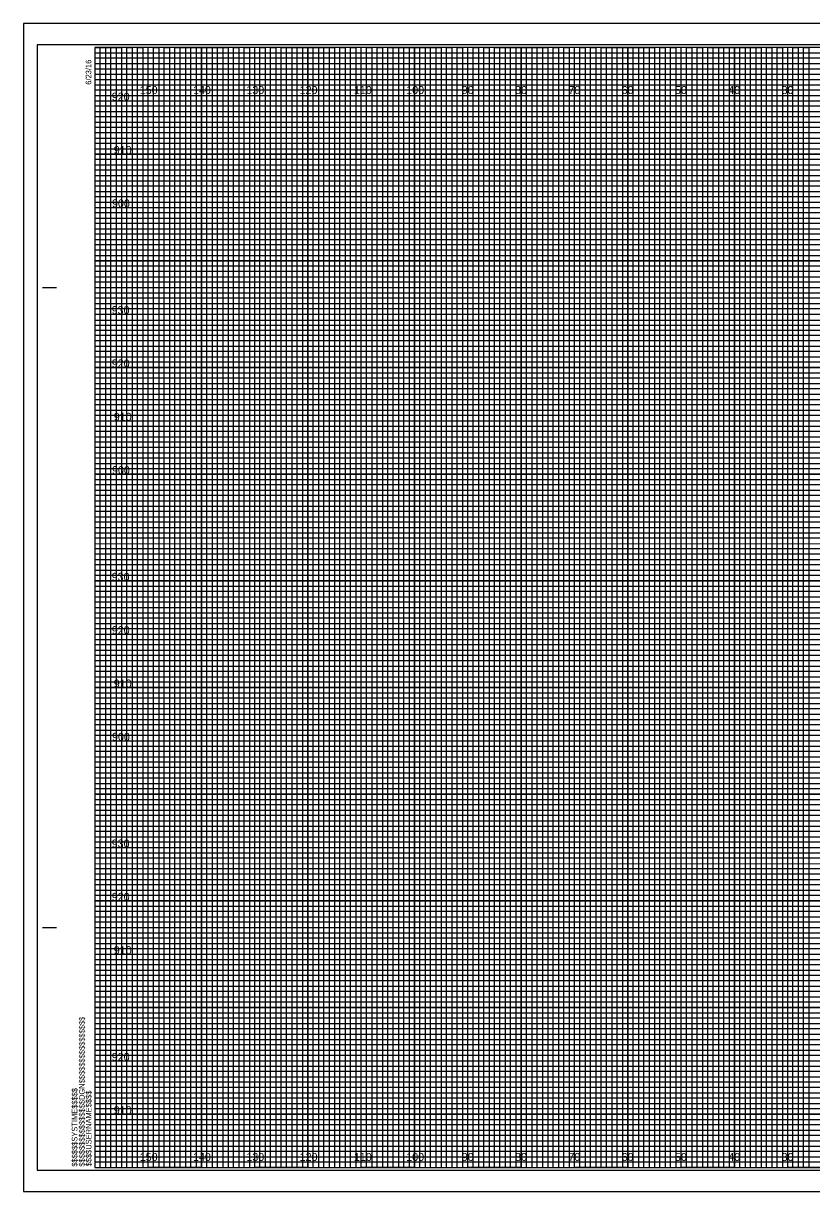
# Model space of a CAD drawing. Extents: x -13 to 323, y -4 to 214.
# Drawn here: x -13.4 to 134.5, y -4.5 to 214.5 of the extents above; entities that cross this region are included whole.
import ezdxf

# ---------------------------------------------------------------- set-up
doc = ezdxf.new("R2010")
doc.units = 0
for name, color, linetype in [('Exist XS Center Line Elevation Label', 7, 'Continuous'), ('Prop XS Elevation Labels', 7, 'Continuous'), ('Sheet Cross Section CELL', 7, 'Continuous'), ('Sheet Cross Section Grid Major CELL', 7, 'Continuous'), ('Sheet Cross Section Grid Middle CELL', 7, 'Continuous'), ('Sheet Cross Section Grid Minor 1 CELL', 7, 'Continuous'), ('Sheet Cross Section Grid Minor 2 CELL', 7, 'Continuous'), ('Sheet Cutting Line CELL', 7, 'Continuous'), ('Sheet DOT Grid CELL', 7, 'Continuous'), ('Sheet Plot Border Inside CELL', 7, 'Continuous'), ('Sheet Plot Border Outside CELL', 7, 'Continuous')]:
    doc.layers.add(name, color=color, linetype=linetype)

msp = doc.modelspace()

# ---------------------------------------------------------------- linework, layer by layer
at = {"layer": 'Sheet Cross Section CELL'}
for p, q in [((-9.8, 165), (-7.3, 165)), ((-9.7, 165), (-7.2, 165)), ((-9.8, 45), (-7.3, 45)), ((-9.7, 45), (-7.2, 45)), ((0, 0), (0, 0)), ((0, 0), (0, 0)), ((0, 0), (0, 0)), ((0, 0), (0, 0)), ((0, 0), (0, 0)), ((0, 0), (0, 0)), ((0, 0), (0, 0))]:
    msp.add_line(p, q, dxfattribs=at)
msp.add_lwpolyline([(320, 210), (0, 210), (0, 0), (320, 0)], close=True, dxfattribs=at)
at = {"layer": 'Sheet Cross Section Grid Major CELL'}
for p, q in [((10, 210), (0, 210)), ((10, 0), (10, 210)), ((30, 210), (20, 210)), ((20, 210), (20, 0)), ((30, 0), (30, 210)), ((50, 210), (40, 210)), ((40, 210), (40, 0)), ((50, 0), (50, 210)), ((70, 210), (60, 210)), ((60, 210), (60, 0)), ((70, 0), (70, 210)), ((90, 210), (80, 210)), ((80, 210), (80, 0)), ((90, 0), (90, 210)), ((110, 210), (100, 210)), ((100, 210), (100, 0)), ((110, 0), (110, 210)), ((130, 210), (120, 210)), ((120, 210), (120, 0)), ((130, 0), (130, 210)), ((20, 0), (10, 0)), ((40, 0), (30, 0)), ((60, 0), (50, 0)), ((80, 0), (70, 0)), ((100, 0), (90, 0)), ((120, 0), (110, 0)), ((140, 0), (130, 0))]:
    msp.add_line(p, q, dxfattribs=at)
for points in [[(0, 200), (320, 200), (320, 190), (0, 190)], [(0, 180), (320, 180), (320, 170), (0, 170)], [(0, 160), (320, 160), (320, 150), (0, 150)], [(0, 140), (320, 140), (320, 130), (0, 130)], [(0, 120), (320, 120), (320, 110), (0, 110)], [(0, 100), (320, 100), (320, 90), (0, 90)], [(0, 80), (320, 80), (320, 70), (0, 70)], [(0, 60), (320, 60), (320, 50), (0, 50)], [(0, 40), (320, 40), (320, 30), (0, 30)], [(0, 20), (320, 20), (320, 10), (0, 10)]]:
    msp.add_lwpolyline(points, dxfattribs=at)
at = {"layer": 'Sheet Cross Section Grid Middle CELL'}
for points in [[(0, 210), (5, 210), (5, 0), (15, 0), (15, 210), (25, 210), (25, 0), (35, 0), (35, 210), (45, 210), (45, 0), (55, 0), (55, 210), (65, 210), (65, 0), (75, 0), (75, 210), (85, 210), (85, 0), (95, 0), (95, 210), (105, 210), (105, 0), (115, 0), (115, 210), (125, 210), (125, 0), (135, 0)], [(0, 205), (275, 205)], [(0, 185), (320, 185), (320, 195), (0, 195)], [(0, 165), (320, 165), (320, 175), (0, 175)], [(0, 145), (320, 145), (320, 155), (0, 155)], [(0, 125), (320, 125), (320, 135), (0, 135)], [(0, 105), (320, 105), (320, 115), (0, 115)], [(0, 85), (320, 85), (320, 95), (0, 95)], [(0, 65), (320, 65), (320, 75), (0, 75)], [(0, 45), (320, 45), (320, 55), (0, 55)], [(0, 25), (320, 25), (320, 35), (0, 35)], [(0, 5), (320, 5), (320, 15), (0, 15)]]:
    msp.add_lwpolyline(points, dxfattribs=at)
at = {"layer": 'Sheet Cross Section Grid Minor 1 CELL'}
for p, q in [((0, 209), (260, 209)), ((260, 207.98), (0, 207.98)), ((0, 207.98), (0, 207)), ((0, 207), (260, 207)), ((260, 205.89), (0, 205.89)), ((0, 205.89), (0, 204)), ((0, 204), (320, 204))]:
    msp.add_line(p, q, dxfattribs=at)
for points in [[(0, 203), (270, 203), (320, 203), (320, 202), (0, 202)], [(0, 201), (320, 201), (320, 199), (0, 199)], [(0, 198), (320, 198), (320, 197), (0, 196.98)], [(0, 196), (320, 196), (320, 194), (0, 194)], [(0, 193), (320, 193), (320, 192), (0, 192)], [(0, 191), (320, 191), (320, 189), (0, 189)], [(0, 188), (320, 188), (320, 187), (0, 187)], [(0, 186), (320, 186), (320, 184), (0, 184)], [(0, 183), (320, 183), (320, 182), (0, 182)], [(0, 181), (320, 181), (320, 179), (0, 179)], [(0, 178), (320, 178), (320, 177), (0, 177)], [(0, 176), (320, 176), (320, 173.95), (320, 173), (320, 172), (0, 172)], [(0, 174), (320, 174), (320, 173), (0, 173)], [(0, 171), (320, 171), (320, 169), (0, 169.03)], [(0, 169.03), (320, 169), (320, 168), (0, 168)], [(0, 167), (320, 167), (320, 166), (0, 166)], [(0, 164), (320, 164), (320, 163), (0, 163)], [(0, 162), (320, 162), (320, 161), (0, 161)], [(-0.07, 158.89), (320, 158.89), (320, 157.88), (-0.07, 157.88)], [(0, 157), (320, 157), (320, 156), (0, 156)], [(0, 154), (320, 154), (320, 153), (0, 153)], [(0, 152), (320, 152), (320, 151), (0, 151)], [(0, 149), (320, 149), (320, 148), (0, 148)], [(0, 147), (320, 147), (320, 146), (0, 146)], [(0, 144), (320, 144), (320, 143), (0, 143)], [(0, 142), (320, 142), (320, 141), (0, 141)], [(0, 139), (320, 139), (319.99, 137.98), (0, 138)], [(0, 137), (320, 137), (320, 136), (0, 136)], [(0, 134), (320, 134), (320, 133), (0, 133)], [(0, 132), (320, 132), (320, 131), (0, 131)], [(0, 129), (320, 129), (320, 128), (0, 128)], [(0, 127), (320, 127), (320, 126), (0, 126)], [(0, 124), (320, 124), (320, 123), (0, 123)], [(0, 122), (320, 122), (320, 121), (0, 121)], [(0, 119), (320, 119), (320, 118), (0, 118)], [(0, 116.99), (320.07, 116.91), (320, 116), (0, 116)], [(0, 114), (320, 114), (320, 113), (0, 113)], [(0, 112), (320, 112), (320, 111), (0, 111)], [(0, 109), (320, 109), (320, 108), (0, 108)], [(0, 107), (320, 107), (320, 106), (0, 106)], [(0, 104), (320, 104), (320, 103), (0, 103)], [(0, 102), (320, 102), (320, 101), (0, 101)], [(0, 99), (320, 99), (320, 98), (0, 98)], [(0, 97), (320, 97), (320, 96), (0, 96)], [(0, 94), (320, 94), (320, 93), (0, 93)], [(0, 92), (320, 92), (320, 91), (0, 91)], [(0, 89), (320, 89), (320, 88), (0, 88)], [(0, 87), (320, 87), (320, 86), (0, 86)], [(0, 84), (320, 84), (320, 83), (0, 83)], [(0, 82), (320, 82), (320, 81), (0, 81)], [(0, 79), (320, 79), (319.99, 77.98), (0, 78)], [(0, 77), (320, 77), (320, 76), (0, 76)], [(0, 74), (320, 74), (320, 73), (0, 73)], [(0, 72), (320, 72), (320, 71), (0, 71)], [(0, 69), (320, 69), (320, 68), (0, 68)], [(0, 67), (320, 67), (320, 66), (0, 66)], [(0, 64), (320, 64), (320, 63), (0, 63)], [(0, 62), (320, 62), (320, 61), (0, 61)], [(0, 59), (320, 59), (320, 58), (0, 58)], [(0, 56.99), (320.07, 56.91), (320, 56), (0, 56)], [(0, 54), (320, 54), (320, 53), (0, 53)], [(0, 52), (320, 52), (320, 51), (0, 51)], [(0, 49), (320, 49), (320, 48), (0, 48)], [(0, 47), (320, 47), (320, 46), (0, 46)], [(0, 44), (320, 44), (320, 43), (0, 43)], [(0, 42), (320, 42), (320, 41), (0, 41)], [(0, 39), (320, 39), (320, 38), (0, 38)], [(0, 37), (320, 37), (320, 36), (0, 36)], [(0, 34), (320, 34), (320, 33), (0, 33)], [(0, 32), (320, 32), (320, 31), (0, 31)], [(0, 29), (320, 29), (320, 28), (0, 28)], [(0, 27), (320, 27), (320, 26), (0, 26)], [(0, 24), (320, 24), (320, 23), (0, 23)], [(0, 22), (320, 22), (320, 21), (0, 21)], [(0, 19), (320, 19), (320, 18), (0, 18)], [(0, 17), (320, 17), (320, 16), (0, 16)], [(0, 14), (320, 14), (320, 13), (0, 13)], [(0, 12), (320, 12), (320, 11), (0, 11)], [(0, 9), (320, 9), (320, 8), (0, 8)], [(0, 7), (320, 7), (320, 6), (0, 6)], [(0, 4), (320, 4), (320, 3), (0, 3)], [(0, 2), (320, 2), (320, 1), (0, 1)]]:
    msp.add_lwpolyline(points, dxfattribs=at)
at = {"layer": 'Sheet Cross Section Grid Minor 2 CELL'}
for points in [[(0, 0), (1, 0), (1, 210), (2, 210), (2, 0)], [(2, 0), (3, 0), (3, 210), (4, 210), (4, 0)], [(5, 0), (6, 0), (6, 210), (7, 210), (7, 0)], [(7, 0), (8, 0), (8, 210), (9, 210), (9, 0)], [(10, 0), (11, 0), (11, 210), (12, 210), (12, 0)], [(12, 0), (13, 0), (13, 210), (14, 210), (14, 0)], [(15, 0), (16, 0), (16, 210), (17, 210), (17, 0)], [(17, 0), (18, 0), (18, 210), (19, 210), (19, 0)], [(20, 0), (21, 0), (21, 210), (22, 210), (22, 0)], [(22, 0), (23, 0), (23, 210), (24, 210), (24, 0)], [(25, 0), (26, 0), (26, 210), (27, 210), (27, 0)], [(27, 0), (28, 0), (28, 210), (29, 210), (29, 0)], [(30, 0), (31, 0), (31, 210), (32, 210), (32, 0)], [(32, 0), (33, 0), (33, 210), (34, 210), (34, 0)], [(35, 0), (36, 0), (36, 210), (37, 210), (37, 0)], [(37, 0), (38, 0), (38, 210), (39, 210), (39, 0)], [(40, 0), (41, 0), (41, 210), (42, 210), (42, 0)], [(42, 0), (43, 0), (43, 210), (44, 210), (44, 0)], [(45, 0), (46, 0), (46, 210), (47, 210), (47, 0)], [(47, 0), (48, 0), (48, 210), (49, 210), (49, 0)], [(50, 0), (51, 0), (51, 210), (52, 210), (52, 0)], [(52, 0), (53, 0), (53, 210), (54, 210), (54, 0)], [(55, 0), (56, 0), (56, 210), (57, 210), (57, 0)], [(57, 0), (58, 0), (58, 210), (59, 210), (59, 0)], [(60, 0), (61, 0), (61, 210), (62, 210), (62, 0)], [(62, 0), (63, 0), (63, 210), (64, 210), (64, 0)], [(65, 0), (66, 0), (66, 210), (67, 210), (67, 0)], [(67, 0), (68, 0), (68, 210), (69, 210), (69, 0)], [(70, 0), (71, 0), (71, 210), (72, 210), (72, 0)], [(72, 0), (73, 0), (73, 210), (74, 210), (74, 0)], [(75, 0), (76, 0), (76, 210), (77, 210), (77, 0)], [(77, 0), (78, 0), (78, 210), (79, 210), (79, 0)], [(80, 0), (81, 0), (81, 210), (82, 210), (82, 0)], [(82, 0), (83, 0), (83, 210), (84, 210), (84, 0)], [(85, 0), (86, 0), (86, 210), (87, 210), (87, 0)], [(87, 0), (88, 0), (88, 210), (89, 210), (89, 0)], [(90, 0), (91, 0), (91, 210), (92, 210), (92, 0)], [(92, 0), (93, 0), (93, 210), (94, 210), (94, 0)], [(95, 0), (96, 0), (96, 210), (97, 210), (97, 0)], [(97, 0), (98, 0), (98, 210), (99, 210), (99, 0)], [(100, 0), (101, 0), (101, 210), (102, 210), (102, 0)], [(102, 0), (103, 0), (103, 210), (104, 210), (104, 0)], [(105, 0), (106, 0), (106, 210), (107, 210), (107, 0)], [(107, 0), (108, 0), (108, 210), (109, 210), (109, 0)], [(110, 0), (111, 0), (111, 210), (112, 210), (112, 0)], [(112, 0), (113, 0), (113, 210), (114, 210), (114, 0)], [(115, 0), (116, 0), (116, 210), (117, 210), (117, 0)], [(117, 0), (118, 0), (118, 210), (119, 210), (119, 0)], [(120, 0), (121, 0), (121, 210), (122, 210), (122, 0)], [(122, 0), (123, 0), (123, 210), (124, 210), (124, 0)], [(125, 0), (126, 0), (126, 210), (127, 210), (127, 0)], [(127, 0), (128, 0), (128, 210), (129, 210), (129, 0)], [(130, 0), (131, 0), (131, 210), (132, 210), (132, 0)], [(132, 0), (133, 0), (133, 210), (134, 210), (134, 0)]]:
    msp.add_lwpolyline(points, dxfattribs=at)
at = {"layer": 'Sheet Cutting Line CELL'}
for p, q in [((323.3, 214.5), (-13.4, 214.5)), ((-13.4, 214.5), (-13.4, -4.5)), ((-13.4, -4.5), (323.3, -4.5))]:
    msp.add_line(p, q, dxfattribs=at)
at = {"layer": 'Sheet DOT Grid CELL'}
for p, q in [((10, 0), (10, 210)), ((20, 0), (20, 210)), ((30, 0), (30, 210)), ((40, 0), (40, 210)), ((50, 0), (50, 210)), ((60, 0), (60, 210)), ((70, 0), (70, 210)), ((80, 0), (80, 210)), ((90, 0), (90, 210)), ((100, 0), (100, 210)), ((110, 0), (110, 210)), ((120, 0), (120, 210)), ((130, 0), (130, 210)), ((0, 200), (320, 200)), ((0, 190), (320, 190)), ((0, 180), (320, 180)), ((0, 170), (320, 170)), ((0, 160), (320, 160)), ((0, 150), (320, 150)), ((0, 140), (320, 140)), ((0, 130), (320, 130)), ((0, 120), (320, 120)), ((0, 110), (320, 110)), ((0, 100), (320, 100)), ((0, 90), (320, 90)), ((0, 80), (320, 80)), ((0, 70), (320, 70)), ((0, 60), (320, 60)), ((0, 50), (320, 50)), ((0, 40), (320, 40)), ((0, 30), (320, 30)), ((0, 20), (320, 20)), ((0, 10), (320, 10))]:
    msp.add_line(p, q, dxfattribs=at)
at = {"layer": 'Sheet Plot Border Inside CELL'}
msp.add_lwpolyline([(-10.8, -0.5), (322.4, -0.5), (322.4, 210.5), (-10.8, 210.5)], close=True, dxfattribs=at)
at = {"layer": 'Sheet Plot Border Outside CELL'}
msp.add_lwpolyline([(-13.4, -4.5), (323.3, -4.5), (323.3, 214.5), (-13.4, 214.5)], close=True, dxfattribs=at)

# ---------------------------------------------------------------- texts
at = {"layer": 'Exist XS Center Line Elevation Label'}
for s, p in [('150', (8.44, 201.25)), ('140', (18.44, 201.25)), ('130', (28.44, 201.25)), ('120', (38.44, 201.25)), ('110', (48.62, 201.25)), ('100', (58.44, 201.25)), ('90', (68.86, 201.25)), ('80', (78.86, 201.25)), ('70', (88.86, 201.25)), ('60', (98.86, 201.25)), ('50', (108.86, 201.25)), ('40', (118.86, 201.25)), ('30', (128.86, 201.25)), ('150', (8.44, 1.25)), ('140', (18.44, 1.25)), ('130', (28.44, 1.25)), ('120', (38.44, 1.25)), ('110', (48.62, 1.25)), ('100', (58.44, 1.25)), ('90', (68.86, 1.25)), ('80', (78.86, 1.25)), ('70', (88.86, 1.25)), ('60', (98.86, 1.25)), ('50', (108.86, 1.25)), ('40', (118.86, 1.25)), ('30', (128.86, 1.25))]:
    msp.add_text(s, height=1.5, dxfattribs=at).set_placement(p)
at = {"layer": 'Prop XS Elevation Labels'}
for s, p in [('920', (3.19, 200)), ('910', (3.57, 190)), ('900', (3.24, 180)), ('930', (3.18, 160)), ('920', (3.19, 150)), ('910', (3.57, 140)), ('900', (3.24, 130)), ('930', (3.18, 110)), ('920', (3.19, 100)), ('910', (3.57, 90)), ('900', (3.24, 80)), ('930', (3.18, 60)), ('920', (3.19, 50)), ('910', (3.57, 40)), ('920', (3.19, 20)), ('910', (3.57, 10))]:
    msp.add_text(s, height=1.5, dxfattribs=at).set_placement(p)
at = {"layer": 'Sheet Cross Section CELL'}
for s, p in [('6/23/16', (-0.65, 203)), ('$$$$$$$$$$$$$$$$DGN$$$$$$$$$$$$$$$$', (-1.88, 0.18)), ('$$$$$$SYSTIME$$$$$', (-3.26, 0.18)), ('$$$$USERNAME$$$$', (-0.62, 0.23))]:
    msp.add_text(s, height=1.05, rotation=90, dxfattribs=at).set_placement(p)

doc.saveas('drawing.dxf')
